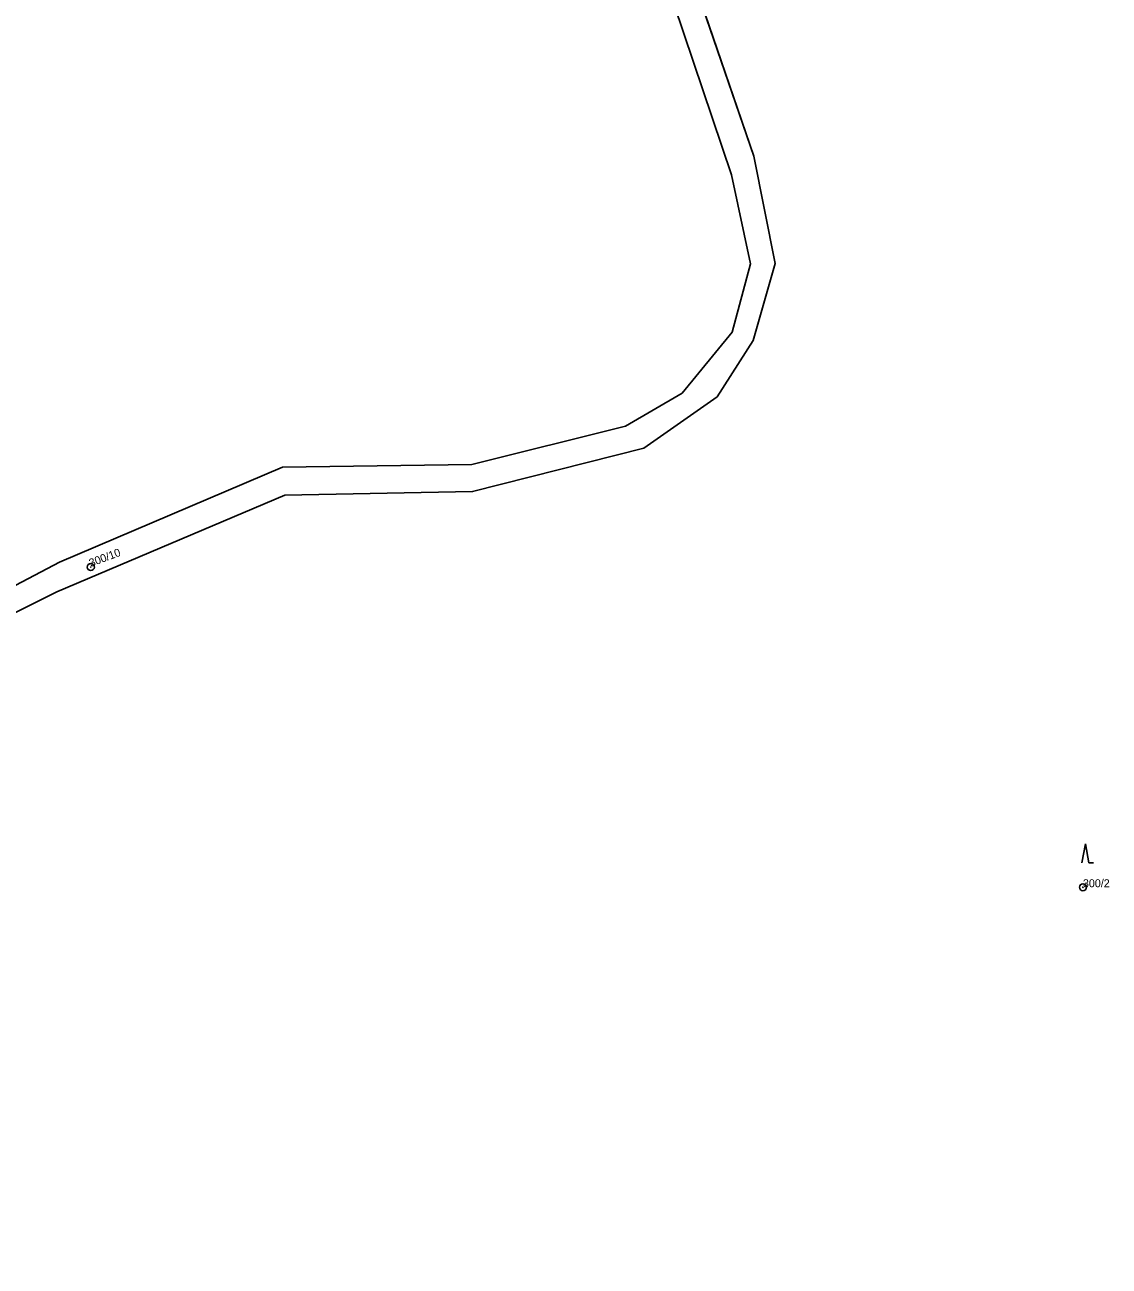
# Model space of a CAD drawing. Extents: x -652854 to -650068, y -1097661 to -1095417.
# Drawn here: x -651701 to -651470.7, y -1097308.5 to -1097044.8 of the extents above; entities that cross this region are included whole.
import ezdxf

# ---------------------------------------------------------------- set-up
doc = ezdxf.new("R2010")
doc.units = 0
for name, color, linetype in [('Definiční body parcel', 7, 'Continuous'), ('Hranice parcel', 7, 'Continuous'), ('Obvody jako plochy', 7, 'Continuous'), ('Parcelní čísla', 7, 'Continuous'), ('Značky kultur', 7, 'Continuous')]:
    doc.layers.add(name, color=color, linetype=linetype)

msp = doc.modelspace()

# ---------------------------------------------------------------- linework, layer by layer
at = {"layer": 'Definiční body parcel'}
for centre, radius in [((-651686.97, -1097159.99), 0.75), ((-651686.97, -1097159.99), 0.0327), ((-651476.23, -1097228.01), 0.75), ((-651476.23, -1097228.01), 0.0327)]:
    msp.add_circle(centre, radius, dxfattribs=at)
at = {"layer": 'Hranice parcel'}
for p, q in [((-651559.09, -1097034.81), (-651546.15, -1097072.72)), ((-651563.08, -1097040.57), (-651550.89, -1097076.68)), ((-651546.15, -1097072.72), (-651541.62, -1097095.49)), ((-651550.89, -1097076.68), (-651546.83, -1097095.59)), ((-651546.83, -1097095.59), (-651550.73, -1097110.1)), ((-651541.62, -1097095.49), (-651546.3, -1097111.84)), ((-651550.73, -1097110.1), (-651561.36, -1097123.06)), ((-651546.3, -1097111.84), (-651553.94, -1097123.82)), ((-651561.36, -1097123.06), (-651573.39, -1097130.09)), ((-651553.94, -1097123.82), (-651569.53, -1097134.74)), ((-651573.39, -1097130.09), (-651606.05, -1097138.21)), ((-651569.53, -1097134.74), (-651605.87, -1097143.94)), ((-651646.28, -1097138.78), (-651693.61, -1097158.93)), ((-651606.05, -1097138.21), (-651646.28, -1097138.78)), ((-651645.74, -1097144.71), (-651694.17, -1097165.26)), ((-651605.87, -1097143.94), (-651645.74, -1097144.71)), ((-651693.61, -1097158.93), (-651747.99, -1097187.53)), ((-651694.17, -1097165.26), (-651745.78, -1097190.99))]:
    msp.add_line(p, q, dxfattribs=at)
at = {"layer": 'Obvody jako plochy'}
for points in [[(-651559.09, -1097034.81), (-651546.15, -1097072.72), (-651541.62, -1097095.49), (-651546.3, -1097111.84), (-651553.94, -1097123.82), (-651569.53, -1097134.74), (-651605.87, -1097143.94), (-651645.74, -1097144.71), (-651694.17, -1097165.26), (-651745.78, -1097190.99)], [(-651745.78, -1097190.99), (-651694.17, -1097165.26), (-651645.74, -1097144.71), (-651605.87, -1097143.94), (-651569.53, -1097134.74), (-651553.94, -1097123.82), (-651546.3, -1097111.84), (-651541.62, -1097095.49), (-651546.15, -1097072.72), (-651559.09, -1097034.81)], [(-651926.46, -1097428.73), (-651906.62, -1097444.67), (-651903.58, -1097459.6), (-651902.87, -1097443.89), (-651906.06, -1097410.33), (-651897.24, -1097391.74), (-651868.68, -1097354.1), (-651863.05, -1097343.32), (-651843.88, -1097321.35), (-651835.59, -1097289.34), (-651799.03, -1097243.39), (-651765.96, -1097199.26), (-651747.99, -1097187.53), (-651693.61, -1097158.93), (-651646.28, -1097138.78), (-651606.05, -1097138.21), (-651573.39, -1097130.09), (-651561.36, -1097123.06), (-651550.73, -1097110.1), (-651546.83, -1097095.59), (-651550.89, -1097076.68), (-651563.08, -1097040.57)], [(-651563.08, -1097040.57), (-651550.89, -1097076.68), (-651546.83, -1097095.59), (-651550.73, -1097110.1), (-651561.36, -1097123.06), (-651573.39, -1097130.09), (-651606.05, -1097138.21), (-651646.28, -1097138.78), (-651693.61, -1097158.93), (-651747.99, -1097187.53)]]:
    msp.add_lwpolyline(points, dxfattribs=at)
at = {"layer": 'Značky kultur'}
for p, q in [((-651475.702, -1097218.819), (-651476.435, -1097222.819)), ((-651475.702, -1097218.819), (-651474.969, -1097222.819)), ((-651474.969, -1097222.819), (-651473.969, -1097222.819))]:
    msp.add_line(p, q, dxfattribs=at)

# ---------------------------------------------------------------- texts
at = {"layer": 'Parcelní čísla'}
msp.add_text('300/10', height=1.7, rotation=20.601, dxfattribs=at).set_placement((-651686.97, -1097159.99))
msp.add_text('300/2', height=1.7, dxfattribs=at).set_placement((-651476.23, -1097228.01))

doc.saveas('drawing.dxf')
